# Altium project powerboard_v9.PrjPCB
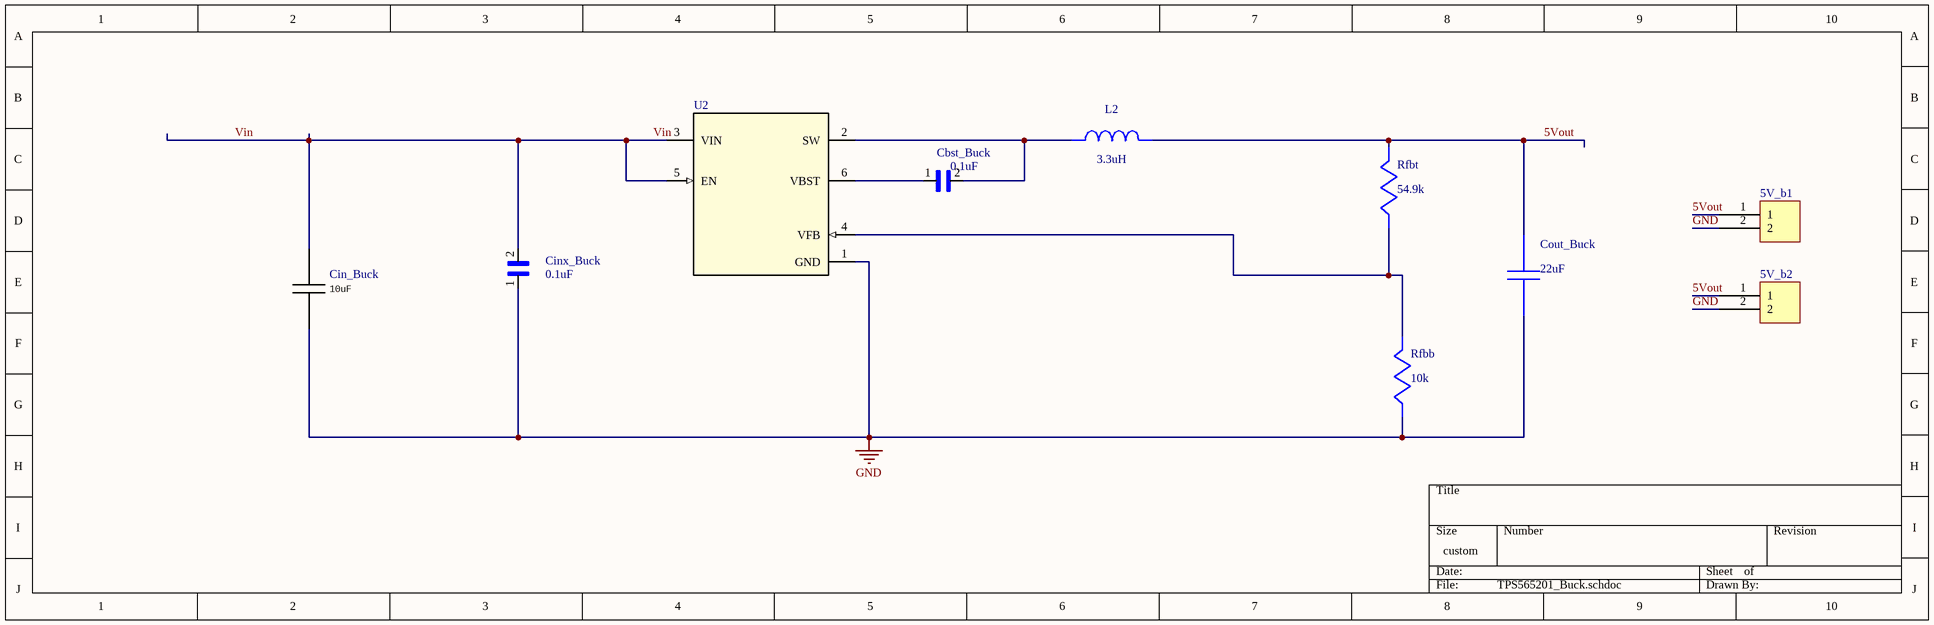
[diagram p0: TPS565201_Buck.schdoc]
3 sheets, 37 parts. Net scope: global (net labels, ports and power ports of the same name join across sheets).
Board files: poweboard_v6.PcbDoc, toggle_switch.PcbDoc
Sheets:
  TPS565201_Buck.schdoc
  LTC3119.schdoc
  Peripherals.SchDoc

## Sheet TPS565201_Buck.schdoc
size 361 x 115 mm; SheetNumber: 1; SheetTotal: 1

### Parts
5V_b1  EBWA-02-A  [EBWA-02-A]  (value not drawn)
5V_b2  EBWA-02-A  [EBWA-02-A]  (value not drawn)
Cbst_Buck  value 0.1uF  [*CAPC1608X90N]  (hidden comment: 100nF)
Cin_Buck  10uF  [1206_190]
Cinx_Buck  value 0.1uF  [*CAPC1608X90N]  (hidden comment: 100nF)
Cout_Buck  22uF  [*CAPC1608X90N]
L2  value 3.3uH  [IHLP-3232DZ]  (hidden comment: IHLP3232DZER3R3M01)
Rfbb  value 10k  [*RESC2012X50N]  (hidden comment: CRCW040210K0FKED)
Rfbt  value 54.9k  [*RESC2012X50N]  (hidden comment: CRCW040254K9FKED)
U2  TPS565201DDCR  [DDC0006A_N]  (value not drawn)

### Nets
GND: 5V_b1.2 5V_b2.2 Cin_Buck.2 Cinx_Buck.1 Cout_Buck.2 Rfbb.2 U2.1(GND)
5Vout: 5V_b1.1 5V_b2.1 Cout_Buck.1 L2.2 Rfbt.1
Vin: Cin_Buck.1 Cinx_Buck.2 U2.3(VIN) U2.5(EN)
NetCbst_Buck_1: Cbst_Buck.1 U2.6(VBST)
NetCbst_Buck_2: Cbst_Buck.2 L2.1 U2.2(SW)
NetRfbb_1: Rfbb.1 Rfbt.2 U2.4(VFB)

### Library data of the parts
Cbst_Buck Cinx_Buck = GRM188R61E104KA01D: SMD Capacitor X5R_EIA_ with Capacitance: 0.10uF Tol. 10%. Rated Voltage: 25Vdc; MF: Murata
Cin_Buck = GRM31CR61E106KA1: Imported; Manufacturer_Part_Number: GRM31CR61E106KA12L; Manufacturer_Name: MuRata; Cap_F: 0.00001; ESR_ohm: 0.004; VDC_V: 25; TYPE_2: TYPE
Cout_Buck = C1608X5R1A226M080AC: C1608X5R1A226M08; Manufacturer Name: TDK
L2 = L1: Unknown; Manufacturer Name: Vishay-Dale
Rfbb = Rfbb: Manufacturer Name: Vishay-Dale
Rfbt = Rfbt: Manufacturer Name: Vishay-Dale
U2 = TPS565201DDCR: Imported; Manufacturer: Texas Instruments

## Sheet LTC3119.schdoc
size A
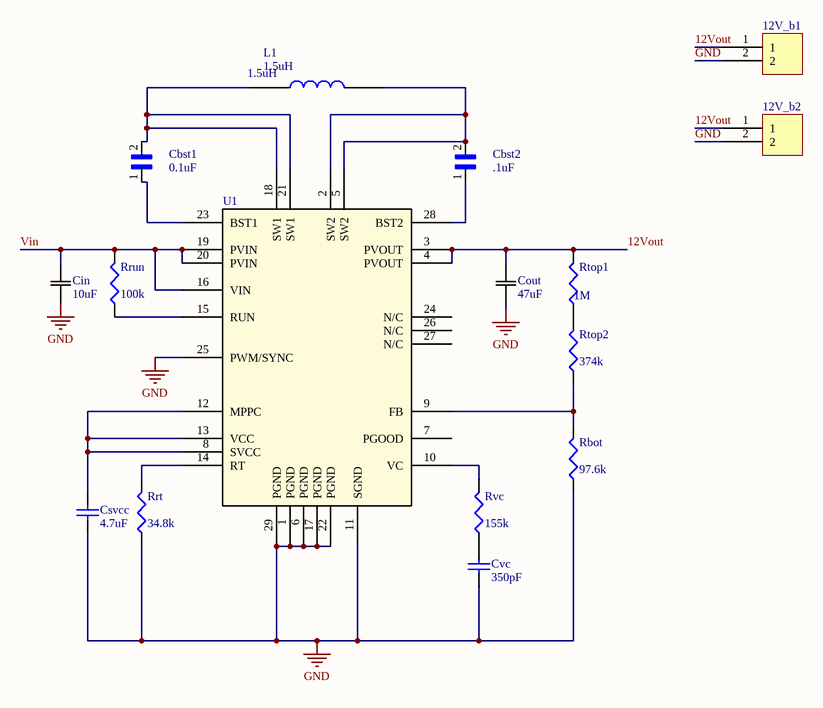
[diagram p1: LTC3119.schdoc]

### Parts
12V_b1  EBWA-02-A  [EBWA-02-A]  (value not drawn)
12V_b2  EBWA-02-A  [EBWA-02-A]  (value not drawn)
Cbst1  value 0.1uF  [*CAPC1608X90N]  (hidden comment: 100nF)
Cbst2  value .1uF  [*CAPC1608X90N]  (hidden comment: 100nF)
Cin  10uF  [1206_190]
Cout  47uF  [1206L]
Csvcc  value 4.7uF  [1608[0603]]  (hidden comment: Cap Semi)
Cvc  value 350pF  [1608[0603]]  (hidden comment: Cap Semi)
L1  1.5uH  [*IND_1217AS-H-1R5N=P3]
Rbot  value 97.6k  [*RESC2012X50N]  (hidden comment: Res3)
Rrt  value 34.8k  [*RESC2012X50N]  (hidden comment: Res3)
Rrun  value 100k  [*RESC2012X50N]  (hidden comment: Res3)
Rtop1  value 1M  [*RESC2012X50N]  (hidden comment: Res3)
Rtop2  value 374k  [*RESC2012X50N]  (hidden comment: Res3)
Rvc  value 155k  [*RESC2012X50N]  (hidden comment: Res3)
U1  LTC3119EUFD#PBF  [QFN28_UFD]  (value not drawn)

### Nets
GND: 12V_b1.2 12V_b2.2 Cin.1 Cout.1 Csvcc.1 Cvc.2 Rbot.1 Rrt.1 U1.1(PGND) U1.6(PGND) U1.11(SGND) U1.17(PGND) U1.22(PGND) U1.25(PWM/SYNC) U1.29(PGND)
12Vout: 12V_b1.1 12V_b2.1 Cout.2 Rtop1.2 U1.3(PVOUT) U1.4(PVOUT)
Vin: Cin.2 Rrun.2 U1.16(VIN) U1.19(PVIN) U1.20(PVIN)
NetCbst1_1: Cbst1.1 U1.23(BST1)
NetCbst1_2: Cbst1.2 L1.1 U1.18(SW1) U1.21(SW1)
NetCbst2_1: Cbst2.1 U1.28(BST2)
NetCbst2_2: Cbst2.2 L1.2 U1.2(SW2) U1.5(SW2)
NetCsvcc_2: Csvcc.2 U1.8(SVCC) U1.12(MPPC) U1.13(VCC)
NetCvc_1: Cvc.1 Rvc.1
NetRbot_2: Rbot.2 Rtop2.1 U1.9(FB)
NetRrt_2: Rrt.2 U1.14(RT)
NetRrun_1: Rrun.1 U1.15(RUN)
NetRtop1_1: Rtop1.1 Rtop2.2
NetRvc_2: Rvc.2 U1.10(VC)

Not connected (* = marked no-connect by the designer): U1 7(PGOOD) 24(N/C) 26(N/C) 27(N/C)

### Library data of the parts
Cbst1 Cbst2 = GRM188R61E104KA01D: as Cbst_Buck on sheet TPS565201_Buck
Cin Cout = TCJY106M035R0070: No Description Available; Vendor: AVX Corporation; Built_By: EMA_UL_Team
Csvcc Cvc = Cap Semi: Capacitor (Semiconductor SIM Model)
L1 = 1217AS-H-1R5N=P3: Inductor with Inductance: 1.5uH Tol. +/-30%, Package: 3131 _8080_; MF: Murata
Rbot Rrt Rrun Rtop1 Rtop2 Rvc = Res3: Resistor
U1 = LTC3119EUFD#PBF: No Description Available

## Sheet Peripherals.SchDoc
size A
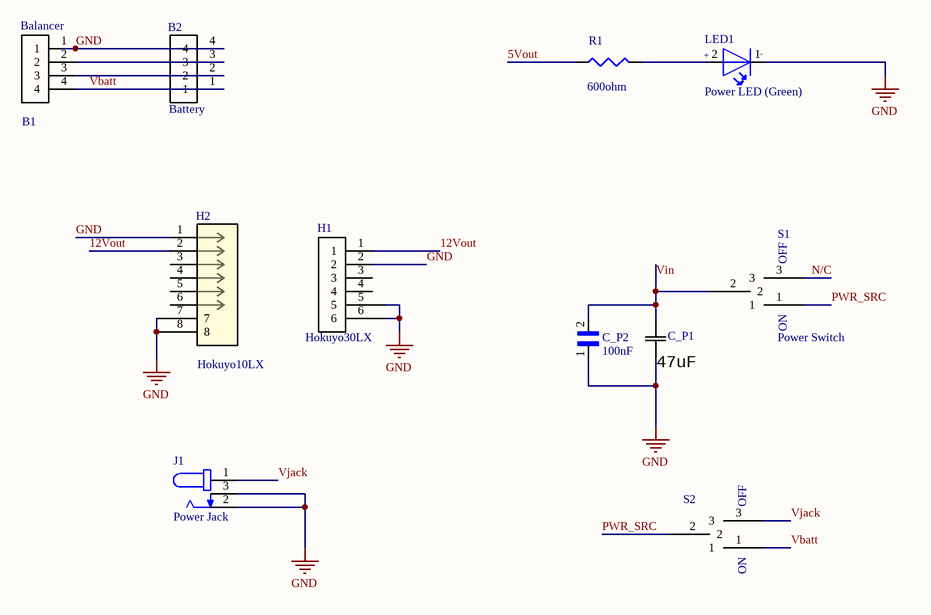
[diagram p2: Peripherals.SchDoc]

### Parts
B1  value Balancer  [*JST_B4B-XH-A(LF)(SN)]  (hidden comment: B4B-XH-A(LF)(SN))
B2  value Battery  [*JST_B4B-XH-A(LF)(SN)]  (hidden comment: B4B-XH-A(LF)(SN))
C_P1  47uF  [1206_190]
C_P2  100nF  [1608[0603]]
H1  Hokuyo30LX  [jst4pin]
H2  Hokuyo10LX  [CONN_BM06B-SRSS-]
J1  Power Jack  [CUI_PJ-036BH-SMT-TR]
LED1  Power LED (Green)  [WL-SMCW_0805]
R1  value 600ohm  [J1-0603]  (hidden comment: Res3)
S1  Power Switch  [E101MD1AQE]
S2  E101MD1AQE  [E101MD1AQE]  (value not drawn)

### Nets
GND: B1.1 B2.4 C_P1.1 C_P2.1 H1.2 H1.5 H1.6 H2.1 H2.7 H2.8 J1.2 J1.3 LED1.1(NEG)
5Vout: R1.1
12Vout: H1.1 H2.2
N/C: S1.3
PWR_SRC: S1.1 S2.2
Vbatt: B1.4 B2.1 S2.1
Vin: C_P1.2 C_P2.2 S1.2
Vjack: J1.1 S2.3
NetB1_2: B1.2 B2.3
NetB1_3: B1.3 B2.2
NetLED1_2: LED1.2(POS) R1.2

Not connected (* = marked no-connect by the designer): H1 3 4; H2 3 4 5 6

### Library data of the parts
B1 B2 = B4B-XH-A(LF)(SN): Connector Header Through Hole 4 position 0.098 _2.50mm_; MP: B4B-XH-A_LF__SN_; MF: JST Sales
C_P1 = TCJY106M035R0070: as Cin on sheet LTC3119
C_P2 = GRM188R61E104KA01D: as Cbst_Buck on sheet TPS565201_Buck
H1 = Component_1
H2 = BM06B-SRSS-TB(LF: No Description Available; Manufacturer_Part_Number: BM06B-SRSS-TB(LF)(SN); Built_By: EMA_Justin; Vendor: JST; SourceLibrary: JST_2020-02-24
J1 = PJ-036BH-SMT-TR: 2.5 x 6.3 mm, 5.0 A, Horizontal, Surface Mount _SMT_, Dc Power Jack Connector; MF: CUI Devices
LED1 = WL-SMCW: Green 520nm LED Indication - Discrete 3.2V 0805 _2012 Metric_; MF: Wurth Electronics; MP: 150080GS75000
R1 = Res3: Resistor
S1 S2 = E101MD1AQE: C&K SWITCH TOGGLE SPDT 7.5A 125V

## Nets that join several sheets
GND: TPS565201_Buck (7 pins), LTC3119 (15 pins), Peripherals (13 pins)
5Vout: TPS565201_Buck (5 pins), Peripherals (R1.1)
12Vout: LTC3119 (6 pins), Peripherals (H1.1 H2.2)
Vin: TPS565201_Buck (Cin_Buck.1 Cinx_Buck.2 U2.3 U2.5), LTC3119 (5 pins), Peripherals (C_P1.2 C_P2.2 S1.2)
